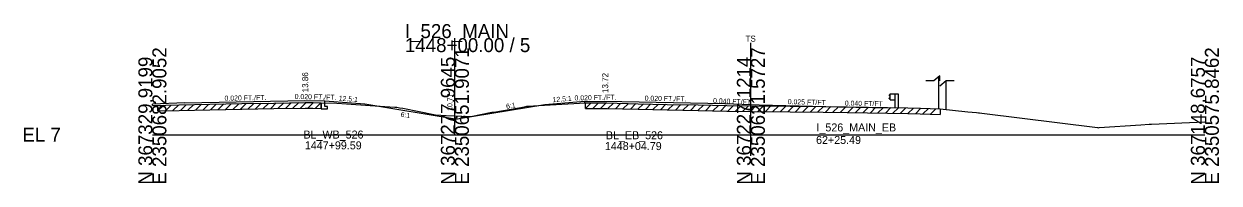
# Model space of a CAD drawing. Extents: x -170 to 2527928, y -10 to 1619750.
# Drawn here: x 4974.3 to 5213.3, y 8490.3 to 8522.2 of the extents above; entities that cross this region are included whole.
import ezdxf

# ---------------------------------------------------------------- set-up
doc = ezdxf.new("R2010")
doc.units = 0
for name, color, linetype in [('Default', 7, 'Continuous'), ('RD_GPK_XS_Cell', 7, 'Continuous'), ('RD_PD_NOISE-WALL-GM', 7, 'Continuous'), ('RD_XS_Base', 7, 'Continuous'), ('RD_XS_EarthShd', 7, 'Continuous'), ('RD_XS_ExGround', 7, 'Continuous'), ('RD_XS_ExPaveRet', 7, 'Continuous'), ('RD_XS_GR', 7, 'Continuous'), ('RD_XS_MatchLine', 7, 'Continuous'), ('RD_XS_Pave', 7, 'Continuous'), ('RD_XS_PaveShd', 7, 'Continuous'), ('RD_XS_TieSlope', 7, 'Continuous'), ('RD_XS_TX_Elev_EX', 7, 'Continuous'), ('RD_XS_TX_Slope', 7, 'Continuous'), ('RD_XS_TX_Station', 7, 'Continuous')]:
    doc.layers.add(name, color=color, linetype=linetype)

msp = doc.modelspace()

# ---------------------------------------------------------------- linework, layer by layer
at = {"layer": 'Default'}
for p, q in [((5156.27, 8510.74), (5154.69, 8510.74)), ((5157.52, 8511.76), (5156.27, 8510.74)), ((5157.52, 8510.74), (5157.52, 8511.76)), ((5158.77, 8510.74), (5157.52, 8509.71)), ((5160.37, 8510.74), (5158.77, 8510.74))]:
    msp.add_line(p, q, dxfattribs=at)
at = {"layer": 'RD_GPK_XS_Cell'}
for p, q in [((5060.5, 8500), (5060.5, 8519.32)), ((5000, 8500), (5060.5, 8500)), ((5060.5, 8500), (5119.7, 8500)), ((5119.7, 8500), (5210.5, 8500))]:
    msp.add_line(p, q, dxfattribs=at)
at = {"layer": 'RD_PD_NOISE-WALL-GM'}
for p, q in [((5157.27, 8505.18), (5157.27, 8511.55)), ((5158.77, 8505.05), (5158.77, 8510.74))]:
    msp.add_line(p, q, dxfattribs=at)
at = {"layer": 'RD_XS_Base'}
for p, q in [((5033.78, 8505.16), (5033.78, 8506.37)), ((5033.78, 8505.16), (5034.5, 8505.15)), ((5034.5, 8505.65), (5034.5, 8506.78)), ((5035, 8505.64), (5034.5, 8505.65)), ((5034.5, 8505.15), (5035, 8505.14)), ((5035, 8505.14), (5035, 8505.64)), ((5086.5, 8506.37), (5086.5, 8506.64))]:
    msp.add_line(p, q, dxfattribs=at)
at = {"layer": 'RD_XS_EarthShd'}
for p, q in [((5034.5, 8506.78), (5042.5, 8506.14)), ((5086.5, 8506.64), (5078.5, 8506))]:
    msp.add_line(p, q, dxfattribs=at)
at = {"layer": 'RD_XS_ExGround'}
msp.add_lwpolyline([(5000, 8505.84), (5005.37, 8505.96), (5011.46, 8506.08), (5017.87, 8506.21), (5024.29, 8506.33), (5030.53, 8506.44), (5032.08, 8506.41), (5033.78, 8506.37), (5036.91, 8506.28), (5038.81, 8506.2), (5043.56, 8505.85), (5048.52, 8505.5), (5048.9, 8505.47), (5049.45, 8505.4), (5050.08, 8505.28), (5056.64, 8503.99), (5058.74, 8503.86), (5060.5, 8503.77), (5063.32, 8503.63), (5063.69, 8503.64), (5067.87, 8504.49), (5068.27, 8504.53), (5074.43, 8505.59), (5074.89, 8505.68), (5075.22, 8505.69), (5077.22, 8505.81), (5086.61, 8506.38), (5087.48, 8506.37), (5090.92, 8506.37), (5097.15, 8506.2), (5102.97, 8506.07), (5109.15, 8505.95), (5114.9, 8505.83), (5119.7, 8505.78), (5127.57, 8505.71), (5134.17, 8505.65), (5138.95, 8505.57), (5151.07, 8505.36), (5153.54, 8505.29), (5157.55, 8505.17), (5163.11, 8504.6), (5164.84, 8504.42), (5165.23, 8504.38), (5165.4, 8504.36), (5165.92, 8504.31), (5189.04, 8501.42), (5189.24, 8501.4), (5189.36, 8501.41), (5197.67, 8501.96), (5199.35, 8502.07), (5199.48, 8502.08), (5199.55, 8502.09), (5199.81, 8502.1), (5210.5, 8502.54)], dxfattribs=at)
at = {"layer": 'RD_XS_ExPaveRet'}
for p, q in [((5001.11, 8504.74), (5002.26, 8505.89)), ((5001.11, 8504.74), (5001.11, 8505.86)), ((5002.61, 8504.78), (5003.76, 8505.93)), ((5004.11, 8504.81), (5005.26, 8505.96)), ((5005.37, 8504.84), (5011.46, 8504.96)), ((5005.61, 8504.85), (5006.76, 8505.99)), ((5007.11, 8504.88), (5008.26, 8506.02)), ((5008.61, 8504.91), (5009.76, 8506.05)), ((5010.11, 8504.93), (5011.26, 8506.08)), ((5011.46, 8504.96), (5017.87, 8505.09)), ((5011.61, 8504.96), (5012.76, 8506.11)), ((5013.11, 8504.99), (5014.26, 8506.14)), ((5014.61, 8505.02), (5015.76, 8506.17)), ((5016.11, 8505.05), (5017.26, 8506.2)), ((5017.61, 8505.09), (5018.76, 8506.23)), ((5017.87, 8505.09), (5024.29, 8505.21)), ((5019.11, 8505.11), (5020.26, 8506.25)), ((5020.61, 8505.14), (5021.76, 8506.28)), ((5022.11, 8505.17), (5023.26, 8506.31)), ((5023.61, 8505.19), (5024.76, 8506.34)), ((5024.29, 8505.21), (5030.53, 8505.32)), ((5025.11, 8505.22), (5026.26, 8506.36)), ((5026.61, 8505.25), (5027.76, 8506.39)), ((5028.11, 8505.28), (5029.26, 8506.42)), ((5029.61, 8505.3), (5030.75, 8506.44)), ((5030.53, 8505.32), (5032.08, 8505.29)), ((5031.11, 8505.31), (5032.21, 8506.41)), ((5032.08, 8505.29), (5033.78, 8505.25)), ((5032.61, 8505.28), (5033.71, 8506.37)), ((5033.78, 8506.37), (5033.78, 8505.25)), ((5086.61, 8505.25), (5086.61, 8506.38)), ((5086.61, 8505.25), (5087.73, 8506.37)), ((5086.61, 8505.25), (5087.48, 8505.25)), ((5087.48, 8505.25), (5090.92, 8505.24)), ((5088.11, 8505.25), (5089.23, 8506.37)), ((5089.61, 8505.25), (5090.73, 8506.37)), ((5090.92, 8505.24), (5097.15, 8505.08)), ((5091.11, 8505.24), (5092.2, 8506.33)), ((5092.61, 8505.2), (5093.7, 8506.29)), ((5094.11, 8505.16), (5095.2, 8506.26)), ((5095.61, 8505.12), (5096.7, 8506.22)), ((5097.11, 8505.08), (5098.2, 8506.18)), ((5097.15, 8505.08), (5102.97, 8504.95)), ((5098.61, 8505.05), (5099.7, 8506.15)), ((5100.11, 8505.02), (5101.2, 8506.11)), ((5101.61, 8504.98), (5102.7, 8506.08)), ((5102.97, 8504.95), (5109.15, 8504.83)), ((5103.11, 8504.95), (5104.21, 8506.05)), ((5104.61, 8504.92), (5105.71, 8506.02)), ((5106.11, 8504.89), (5107.21, 8505.99)), ((5107.61, 8504.86), (5108.71, 8505.96)), ((5109.11, 8504.83), (5110.21, 8505.93)), ((5110.61, 8504.8), (5111.71, 8505.9)), ((5112.11, 8504.77), (5113.21, 8505.86)), ((5113.61, 8504.73), (5114.71, 8505.83)), ((5115.11, 8504.7), (5116.22, 8505.81)), ((5116.61, 8504.69), (5117.72, 8505.8)), ((5118.11, 8504.68), (5119.22, 8505.79)), ((5119.61, 8504.66), (5120.72, 8505.77)), ((5121.11, 8504.65), (5122.22, 8505.76)), ((5122.61, 8504.63), (5123.72, 8505.74)), ((5124.11, 8504.62), (5125.22, 8505.73)), ((5125.61, 8504.61), (5126.72, 8505.72)), ((5127.11, 8504.59), (5128.22, 8505.7)), ((5128.61, 8504.58), (5129.72, 8505.69)), ((5130.11, 8504.57), (5131.22, 8505.68)), ((5131.61, 8504.55), (5132.72, 8505.66)), ((5133.11, 8504.54), (5134.22, 8505.65)), ((5134.61, 8504.52), (5135.71, 8505.62)), ((5136.11, 8504.5), (5137.21, 8505.6)), ((5137.61, 8504.47), (5138.71, 8505.57)), ((5139.11, 8504.44), (5140.21, 8505.55)), ((5140.61, 8504.42), (5141.71, 8505.52)), ((5142.11, 8504.39), (5143.21, 8505.5)), ((5143.61, 8504.37), (5144.71, 8505.47)), ((5145.11, 8504.34), (5146.21, 8505.44)), ((5146.61, 8504.32), (5147.71, 8505.42)), ((5148.11, 8504.29), (5149.21, 8505.39)), ((5149.61, 8504.27), (5150.71, 8505.37)), ((5151.11, 8504.24), (5152.2, 8505.33)), ((5152.61, 8504.2), (5153.7, 8505.29)), ((5154.11, 8504.15), (5155.2, 8505.24)), ((5155.61, 8504.11), (5156.7, 8505.19)), ((5157.55, 8505.17), (5157.55, 8504.05)), ((5001.11, 8504.74), (5005.37, 8504.84)), ((5109.15, 8504.83), (5114.9, 8504.71)), ((5114.9, 8504.71), (5119.7, 8504.66)), ((5119.7, 8504.66), (5127.57, 8504.59)), ((5127.57, 8504.59), (5134.17, 8504.53)), ((5134.17, 8504.53), (5138.95, 8504.45)), ((5138.95, 8504.45), (5151.07, 8504.24)), ((5151.07, 8504.24), (5153.54, 8504.17)), ((5153.54, 8504.17), (5157.55, 8504.05))]:
    msp.add_line(p, q, dxfattribs=at)
at = {"layer": 'RD_XS_GR'}
for p, q in [((5147.55, 8508.08), (5147.38, 8507.88)), ((5147.38, 8507.88), (5147.38, 8507.83)), ((5147.38, 8507.83), (5147.55, 8507.63)), ((5147.38, 8507.31), (5147.55, 8507.51)), ((5147.55, 8506.99), (5147.55, 8508.15)), ((5147.55, 8508.15), (5148.46, 8508.15)), ((5148.46, 8508.15), (5149.13, 8508.15)), ((5148.46, 8508.15), (5148.46, 8505.41)), ((5149.13, 8508.15), (5149.13, 8505.36)), ((5147.38, 8507.26), (5147.38, 8507.31)), ((5147.55, 8507.06), (5147.38, 8507.26)), ((5147.55, 8506.99), (5148.46, 8506.99))]:
    msp.add_line(p, q, dxfattribs=at)
at = {"layer": 'RD_XS_MatchLine'}
msp.add_line((5119.71, 8495.76), (5119.71, 8518.35), dxfattribs=at)
at = {"layer": 'RD_XS_Pave'}
for p, q in [((5006.5, 8506.38), (5030.5, 8506.86)), ((5090.5, 8506.72), (5114.5, 8506.24)), ((5121.36, 8505.97), (5137.38, 8505.56))]:
    msp.add_line(p, q, dxfattribs=at)
at = {"layer": 'RD_XS_PaveShd'}
for p, q in [((5006.5, 8506.38), (5000, 8506.12)), ((5000, 8505.84), (5000, 8506.12)), ((5030.5, 8506.86), (5034.5, 8506.78)), ((5086.5, 8506.64), (5090.5, 8506.72)), ((5114.5, 8506.24), (5121.36, 8505.97)), ((5137.38, 8505.56), (5147.38, 8505.38))]:
    msp.add_line(p, q, dxfattribs=at)
at = {"layer": 'RD_XS_TieSlope'}
for p in [(5042.5, 8506.14), (5078.5, 8506)]:
    msp.add_line(p, (5060.93, 8503.07), dxfattribs=at)

# ---------------------------------------------------------------- texts
at = {"layer": 'RD_GPK_XS_Cell'}
for s, p in [('I_526_MAIN', (5050.5, 8519.32)), ('1448+00.00 / 5', (5050.5, 8516.52)), ('EL 7', (4974, 8498.6))]:
    msp.add_text(s, height=2.8, dxfattribs=at).set_placement(p)
for s, p in [('E 2350682.9052', (5002.8, 8490)), ('E 2350651.9071', (5063.3, 8490)), ('E 2350621.5727', (5122.5, 8490)), ('E 2350575.8462', (5213.3, 8490)), ('N 367329.9199', (5000, 8490)), ('N 367277.9645', (5060.5, 8490)), ('N 367227.1214', (5119.7, 8490)), ('N 367148.6757', (5210.5, 8490))]:
    msp.add_text(s, height=2.8, rotation=90, dxfattribs=at).set_placement(p)
at = {"layer": 'RD_XS_MatchLine'}
msp.add_text('TS', height=1.2, dxfattribs=at).set_placement((5118.63, 8518.62))
at = {"layer": 'RD_XS_TX_Elev_EX'}
msp.add_text('10.77', height=1, rotation=90, dxfattribs=at).set_placement((5060, 8504.77))
at = {"layer": 'RD_XS_TX_Slope'}
for s, rotation, p in [('0.020 FT./FT.', 1.1458, (5014.44, 8506.79)), ('0.020 FT./FT.', 358.8542, (5028.45, 8507.15)), ('12.5:1', 355.4261, (5037.25, 8506.82)), ('12.5:1', 4.5739, (5080.08, 8506.48)), ('0.020 FT./FT.', 1.1458, (5084.44, 8506.85)), ('0.020 FT./FT.', 358.8542, (5098.45, 8506.81)), ('6:1', 9.4623, (5070.83, 8505.15)), ('0.040 FT/FT', 357.7094, (5112.13, 8506.32)), ('0.025 FT/FT', 358.5427, (5127.07, 8506.12)), ('0.040 FT/FT', 359.1102, (5138.48, 8505.81)), ('6:1', 350.5446, (5049.6, 8503.61))]:
    msp.add_text(s, height=1, rotation=rotation, dxfattribs=at).set_placement(p)
at = {"layer": 'RD_XS_TX_Station'}
for s, p in [(' 13.86', (5031.16, 8508.03)), (' 13.72', (5091.16, 8507.89))]:
    msp.add_text(s, height=1.2, rotation=90, dxfattribs=at).set_placement(p)
for s, p in [('BL_WB_526', (5030.21, 8499.22)), ('BL_EB_526', (5090.7, 8499.08)), ('I_526_MAIN_EB', (5132.82, 8500.65)), ('1447+99.59', (5030.5, 8497.06)), ('1448+04.79', (5090.5, 8496.92)), ('62+25.49', (5132.74, 8498.14))]:
    msp.add_text(s, height=1.6, dxfattribs=at).set_placement(p)

doc.saveas('drawing.dxf')
